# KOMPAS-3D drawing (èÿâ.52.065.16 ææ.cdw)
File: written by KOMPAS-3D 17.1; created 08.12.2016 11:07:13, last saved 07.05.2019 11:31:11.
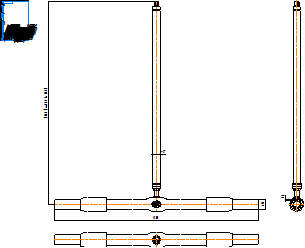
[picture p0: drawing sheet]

Sheet 1: A4, portrait

Title block, sheet 1: name: КШГ.52.065.16 СС; material: Внимание! Данный продукт является объектом авторского права ООО «Торговый Дом АДЛ». / Запрещается изменение, копирование, распространение / (в том числе путем копирования на другие сайты и ресурсы в Интернете) / или любое иное использование информации и объектов без предварительного / согласия правообладателя (ООО «Торговый Дом АДЛ»).; sheets: 1; organisation: ООО "Торговый дом АДЛ"; sheet format: A4; stored path: C:\Users\kka\KOMPAS_Work\Модели кранов для исследований\DN65\С удлинением\КШГ.35.050.25 СС ГЧ _ Шаровой кран БИВАЛ Ду50 Ру2,5 МПа полнопроходной под приварку, c удлинением штока H=950 Габаритный чертеж Lстр600.cdw; drawn by: Климкович К.А.; drawn by, date: 07.12.16

Views: Вид 1, Проекционный вид 2
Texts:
  Klimkovich
  ADL
  (от 287 до 5000)
Dimensions and other numbers on the sheet: 1500; 57; 75; 8,4; 1:1; 1; 07.12.16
